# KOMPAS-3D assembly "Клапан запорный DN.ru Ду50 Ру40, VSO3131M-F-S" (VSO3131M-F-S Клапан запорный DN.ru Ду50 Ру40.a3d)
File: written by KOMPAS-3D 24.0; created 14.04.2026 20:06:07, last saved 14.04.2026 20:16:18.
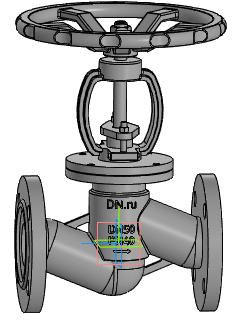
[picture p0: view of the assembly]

Document properties: Автор: R2D2; Полное имя файла: E:\Работа\Зайцев\VSO3131M-F-S Клапан запорный DN.ru Ду15-100 Ру40\DN50\исходные материалы\VSO3131M-F-S Клапан запорный DN.ru Ду50 Ру40.a3d

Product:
- Component [detail]: Корпус  | qty 1  | pos. 1  | Масса: 6.9; Автор: R2D2; source file: Корпус.m3d
- Component [detail]: Клапан запорный DN.ru Ду50 Ру16  | designation VSO1121M-F-S  | qty 1  | pos. 2  | Масса: 14.13; Раздел спецификации: Прочие изделия; Примечание: D090-01947; Автор: R2D2; source file: 2.m3d
- Part/product: Клапан запорный DN.ru Ду50 Ру40  | designation VSO3131M-F-S
    Масса: 11.97
    Раздел спецификации: Прочие изделия
    Примечание: D090-02142

Referenced files in E:\Работа\Зайцев\VSO3131M-F-S Клапан запорный DN.ru Ду15-100 Ру40\DN50\исходные материалы\: Корпус.m3d, 2.m3d
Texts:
  VSO3131M-F-S
  VSO1121M-F-S Клапан запорный DN.ru Ду50 Ру16
  Ось Y.Начало координат
  Плоскость XY.Начало координат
